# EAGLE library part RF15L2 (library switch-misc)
RAFI SWITCH
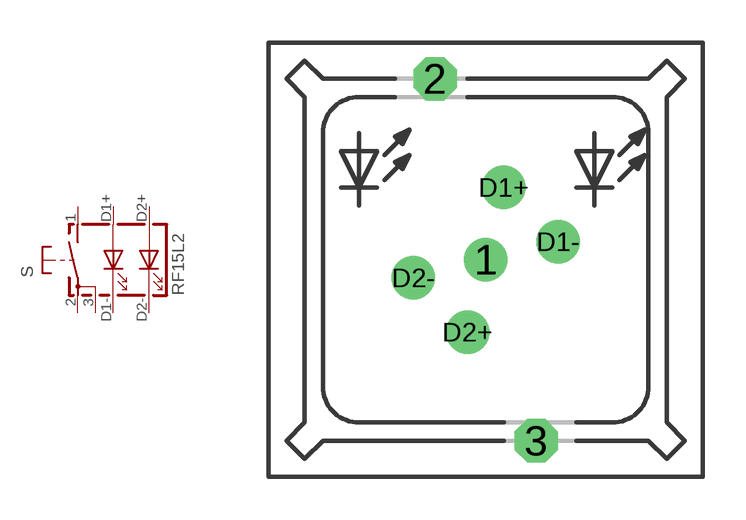
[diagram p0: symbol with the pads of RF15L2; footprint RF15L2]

Designator prefix S

## RF15L2  [RF15L2]
1  S  pas
2  P  pas
3  P  pas
D1+  A1  pas
D1-  C1  pas
D2+  A2  pas
D2-  C2  pas

## Footprint RF15L2 (pad centres in mm)
RAFI SWITCH
drill 1.016 round: 1 0,0; D1+ 0.635,2.54; D1- 2.54,0.635; D2+ -0.635,-2.54; D2- -2.54,-0.635
drill 1.016 octagon: 2 -1.778,6.35; 3 1.778,-6.35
